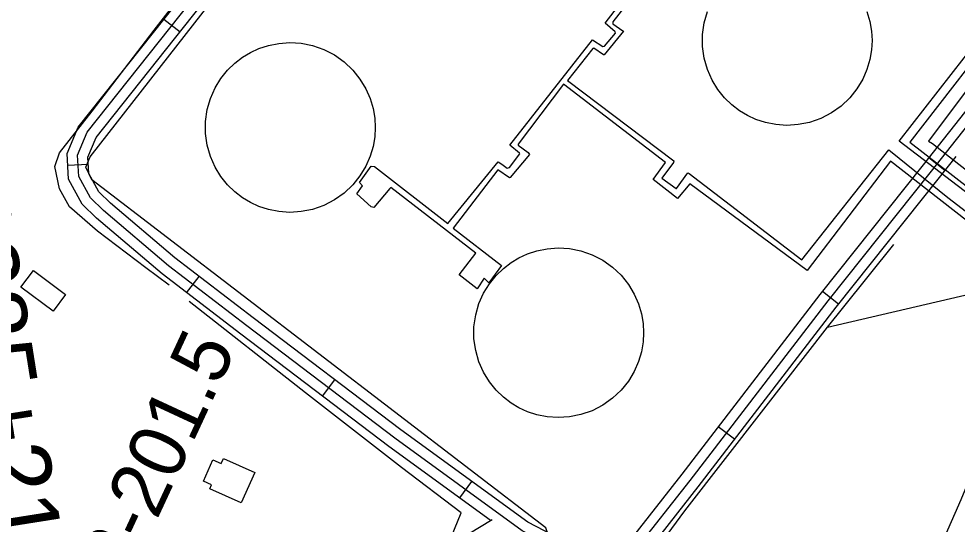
# Model space of a CAD drawing. Extents: x 3329332 to 3367211, y 631066 to 656469.
# Drawn here: x 3347258 to 3348632, y 645877 to 646618 of the extents above; entities that cross this region are included whole.
import ezdxf

# ---------------------------------------------------------------- set-up
doc = ezdxf.new("R2010")
doc.units = 0
for name, color, linetype in [('V-BLDG-OTLN', 7, 'Continuous'), ('V-DOMW-TANK', 7, 'Continuous'), ('V-RIVR-RANG-IDEN', 7, 'Continuous'), ('V-ROAD-CNTR', 7, 'Continuous'), ('V-SITE-OTLN', 7, 'Continuous'), ('V-SURV-IDEN', 7, 'Continuous'), ('V-TOPO-SHOR', 7, 'Continuous'), ('V-UTIL-LINE', 7, 'Continuous')]:
    doc.layers.add(name, color=color, linetype=linetype)

msp = doc.modelspace()

# ---------------------------------------------------------------- linework, layer by layer
at = {"layer": 'V-BLDG-OTLN'}
for points in [[(3347279.6, 646248.8), (3347326.4, 646213.6), (3347308.3, 646189.5), (3347261.4, 646224.7)], [(3347557.7, 645973.3), (3347603.6, 645952.9), (3347583.9, 645908.6), (3347537.9, 645929), (3347540.6, 645935.1), (3347528.6, 645940.4), (3347542.4, 645971.5), (3347554.5, 645966.1)]]:
    msp.add_lwpolyline(points, close=True, dxfattribs=at)
at = {"layer": 'V-DOMW-TANK'}
msp.add_lwpolyline([(3348500.2, 646628.3), (3348504.5, 646613.7), (3348506.9, 646599.6), (3348507.6, 646586), (3348506.9, 646572.4), (3348504.5, 646558.3), (3348500.2, 646543.7), (3348493.9, 646529.2), (3348485.5, 646515.1), (3348474.9, 646501.9), (3348462.3, 646490), (3348448, 646479.8), (3348432.4, 646471.8), (3348416, 646466), (3348399.2, 646462.7), (3348382.6, 646461.7), (3348366.6, 646462.8), (3348351.5, 646465.8), (3348337.6, 646470.4), (3348325, 646476.2), (3348313.5, 646483.1), (3348302.3, 646491.6), (3348291.6, 646502), (3348281.8, 646514.2), (3348273.3, 646528), (3348266.5, 646543.4), (3348261.7, 646559.9), (3348259.3, 646577.2), (3348259.3, 646594.8), (3348261.7, 646612.1), (3348266.5, 646628.6)], dxfattribs=at)
for points in [[(3347780, 646458.6), (3347779.3, 646445), (3347776.9, 646430.8), (3347772.6, 646416.3), (3347766.3, 646401.8), (3347757.8, 646387.7), (3347747.2, 646374.4), (3347734.6, 646362.5), (3347720.3, 646352.4), (3347704.8, 646344.3), (3347688.3, 646338.6), (3347671.6, 646335.3), (3347654.9, 646334.2), (3347638.9, 646335.4), (3347623.8, 646338.4), (3347609.9, 646342.9), (3347597.4, 646348.7), (3347585.9, 646355.7), (3347574.7, 646364.2), (3347564, 646374.6), (3347554.2, 646386.7), (3347545.7, 646400.6), (3347538.8, 646416), (3347534.1, 646432.5), (3347531.6, 646449.8), (3347531.6, 646467.4), (3347534.1, 646484.7), (3347538.8, 646501.2), (3347545.7, 646516.6), (3347554.2, 646530.4), (3347564, 646542.6), (3347574.7, 646552.9), (3347585.9, 646561.5), (3347597.4, 646568.4), (3347609.9, 646574.2), (3347623.8, 646578.8), (3347638.9, 646581.8), (3347654.9, 646582.9), (3347671.6, 646581.9), (3347688.3, 646578.6), (3347704.8, 646572.8), (3347720.3, 646564.8), (3347734.6, 646554.6), (3347747.2, 646542.7), (3347757.8, 646529.5), (3347766.3, 646515.4), (3347772.6, 646500.8), (3347776.9, 646486.3), (3347779.3, 646472.1)], [(3348173.1, 646157.7), (3348172.3, 646144.2), (3348170, 646130), (3348165.7, 646115.5), (3348159.4, 646101), (3348150.9, 646086.8), (3348140.3, 646073.6), (3348127.7, 646061.7), (3348113.4, 646051.6), (3348097.8, 646043.5), (3348081.4, 646037.8), (3348064.6, 646034.4), (3348048, 646033.4), (3348032, 646034.5), (3348016.9, 646037.5), (3348003, 646042.1), (3347990.5, 646047.9), (3347979, 646054.8), (3347967.8, 646063.4), (3347957.1, 646073.7), (3347947.3, 646085.9), (3347938.8, 646099.8), (3347931.9, 646115.1), (3347927.2, 646131.7), (3347924.7, 646149), (3347924.7, 646166.5), (3347927.2, 646183.8), (3347931.9, 646200.4), (3347938.8, 646215.7), (3347947.3, 646229.6), (3347957.1, 646241.7), (3347967.8, 646252.1), (3347979, 646260.7), (3347990.5, 646267.6), (3348003, 646273.4), (3348016.9, 646277.9), (3348032, 646280.9), (3348048, 646282.1), (3348064.6, 646281.1), (3348081.4, 646277.7), (3348097.8, 646272), (3348113.4, 646263.9), (3348127.7, 646253.8), (3348140.3, 646241.9), (3348150.9, 646228.6), (3348159.4, 646214.5), (3348165.7, 646200), (3348170, 646185.5), (3348172.3, 646171.3)]]:
    msp.add_lwpolyline(points, close=True, dxfattribs=at)
at = {"layer": 'V-ROAD-CNTR'}
for p, q in [((3347470.8, 646617.5), (3347494.3, 646598.9)), ((3347330.1, 646403.5), (3347360, 646405)), ((3348614.1, 646395.4), (3348590.5, 646414)), ((3347504, 646216.4), (3347522.2, 646240.2)), ((3348458.3, 646199.8), (3348434.9, 646218.4)), ((3347702.9, 646064.8), (3347721, 646088.7)), ((3348306.1, 646001.8), (3348282.3, 646020.1)), ((3347903.9, 645915.7), (3347921.5, 645939.9))]:
    msp.add_line(p, q, dxfattribs=at)
for points in [[(3348699.8, 648083.5), (3349088.4, 647776.5), (3349399.5, 647541.5), (3349419.1, 647509), (3349423.8, 647475), (3349412.3, 647441.3), (3349161.9, 647117.9), (3348937.1, 646838.3), (3348751.8, 646594.2), (3348594.4, 646394.7), (3348442.9, 646204.5), (3348240.8, 645941.3), (3348159.4, 645837.5), (3348124, 645794.7)], [(3348691.9, 648070.6), (3349079.3, 647764.6), (3349388.2, 647531.3), (3349404.7, 647503.9), (3349408.5, 647476.5), (3349398.9, 647448.5), (3349150.1, 647127.2), (3348925.3, 646847.5), (3348739.9, 646603.4), (3348582.6, 646404), (3348431.1, 646213.7), (3348228.9, 645950.5), (3348152.7, 645853.3)], [(3347948.4, 645883.3), (3347799.9, 645991.2), (3347583.1, 646155.7), (3347468, 646244), (3347372, 646325.6), (3347351.2, 646346.1), (3347331.1, 646382.7), (3347329.2, 646420.6), (3347345.1, 646459.1), (3347618.9, 646804.1), (3347951.1, 647231.7), (3348021, 647331.4), (3348308.8, 647701.3), (3348362.7, 647769.6), (3348463.5, 647894.9)], [(3348774.4, 645336.9), (3348736.7, 645375.5), (3348692.9, 645416.3), (3348640.3, 645440.7), (3348573.2, 645483.2), (3348460.3, 645542.1), (3348215.7, 645738.4), (3348118.5, 645798.1), (3348057.1, 645835.2), (3347995.4, 645867.7), (3347808.9, 646003.2), (3347592.2, 646167.7), (3347477.5, 646255.6), (3347382.2, 646336.7), (3347363.3, 646355.3), (3347345.9, 646386.9), (3347344.4, 646418), (3347358.2, 646451.5), (3347630.7, 646794.9), (3347963.2, 647222.8), (3348033.1, 647322.5), (3348320.6, 647692), (3348374.4, 647760.2), (3348475.2, 647885.5)], [(3348119.1, 645815.3), (3348064.5, 645848.3), (3348003.4, 645880.4), (3347817.8, 646015.3), (3347601.3, 646179.6), (3347486.9, 646267.3), (3347392.3, 646347.8), (3347375.4, 646364.4), (3347360.7, 646391.1), (3347359.5, 646415.3), (3347371.3, 646443.8), (3347642.5, 646785.6), (3347975.2, 647213.9), (3348045.2, 647313.6), (3348332.4, 647682.8), (3348386.1, 647750.9), (3348486.9, 647876.2)], [(3348630.5, 646416.2), (3348606.1, 646385.4), (3348454.8, 646195.3), (3348252.6, 645932.1), (3348177.1, 645835.8)], [(3348131.1, 645498.7), (3347974, 645620.5), (3347852.7, 645707), (3347841, 645737.3), (3347851.4, 645771.7), (3347916.7, 645863.1), (3347951.5, 645883.9)]]:
    msp.add_lwpolyline(points, dxfattribs=at)
at = {"layer": 'V-SITE-OTLN'}
for points in [[(3349704.8, 644526.5), (3349555.3, 644318.8), (3348877.5, 644783.3), (3348501.3, 645063.4), (3348672.5, 645295.1), (3348663.9, 645328.8), (3348637.1, 645365.8), (3348053.2, 645798.4), (3348030, 645871.8), (3347365.1, 646381.8), (3347356.3, 646400.3), (3347362.6, 646415.4), (3348646.5, 648060.7)], [(3348664.9, 648063.5), (3349371.7, 647510.1), (3349380.6, 647494.8), (3348590.2, 646438.5), (3348596.3, 646435.3), (3349236.9, 645931.8), (3349279, 645897.6), (3349765.2, 646596.4)]]:
    msp.add_lwpolyline(points, dxfattribs=at)
at = {"layer": 'V-TOPO-SHOR'}
for points in [[(3347478.6, 646227.3), (3347444, 646252.8), (3347373.4, 646306.8), (3347332.6, 646342.5), (3347317.7, 646368.9), (3347311.2, 646401.5), (3347317.9, 646421.2), (3347365.4, 646482.3), (3347456.6, 646601.3), (3347640.1, 646837.5), (3347729.9, 646953.3), (3347864.7, 647127.8), (3347951.8, 647236.1), (3348022.2, 647331.2), (3348264.4, 647644.9), (3348360.7, 647768.3), (3348525.3, 647979.3), (3348611.9, 648091.4)], [(3348153.6, 645787.7), (3348233.7, 645896.7), (3348348.9, 646045.9), (3348442.5, 646165.7), (3348466.1, 646195.8), (3348539.6, 646287.1)], [(3348442.5, 646165.7), (3348767, 646241.5), (3348780.9, 646272.5)], [(3348477.7, 645543.8), (3348502.6, 645602.7), (3348533.1, 645677.4), (3348571.1, 645763.2), (3348600.9, 645829), (3348638.2, 645913.5), (3348655.5, 645955.7), (3348678.1, 646015.2), (3348706.3, 646082.4), (3348737.1, 646158.1), (3348767, 646241.5)], [(3347694.7, 645403.6), (3347724.5, 645468.8), (3347779.5, 645600.5), (3347828.5, 645716.4), (3347876.7, 645822.1), (3347905.9, 645893.7), (3347818.4, 645960.1), (3347677.9, 646069.5), (3347507.9, 646203.5)]]:
    msp.add_lwpolyline(points, dxfattribs=at)
at = {"layer": 'V-UTIL-LINE'}
for points in [[(3347959.7, 646396.5), (3347894.3, 646311), (3347964.8, 646256.2), (3347946.7, 646230.8), (3347939.5, 646237.7), (3347929.5, 646222), (3347903, 646242.5), (3347927.3, 646274.5), (3347803.2, 646370.4), (3347801.3, 646369.2), (3347778.3, 646341.5), (3347774, 646342.2), (3347753, 646361.4), (3347761.7, 646372.9), (3347756.9, 646377.8), (3347774.4, 646401.9), (3347779.2, 646401.2), (3347886.5, 646317.8), (3347959.9, 646408.1), (3347965.3, 646405), (3347973.2, 646398.8), (3347976.8, 646399.9), (3347991.8, 646419.8), (3347991.2, 646421), (3347977.4, 646432.8), (3348098.1, 646587.1), (3348113.2, 646577.1), (3348115.7, 646577.6), (3348131.9, 646596.9), (3348131.3, 646598.7), (3348116.8, 646611.2), (3348187.8, 646704)], [(3348194.5, 646699), (3348127.8, 646613.4), (3348127.8, 646610.4), (3348142.9, 646600.4), (3348143.5, 646599.8), (3348115.5, 646564.8), (3348114.3, 646564.8), (3348100.4, 646574.8), (3348098.6, 646574.2), (3348061.8, 646527.3), (3348217.3, 646409.5), (3348216.7, 646407.1), (3348199.8, 646384.2), (3348220.9, 646369.2), (3348221.5, 646369.2), (3348237.8, 646392.1), (3348239.6, 646390.9), (3348404.7, 646264.4), (3348532.3, 646425.8), (3348534.7, 646424), (3348618.4, 646356.1), (3348646.1, 646335)], [(3348659.2, 646353.1), (3348547.1, 646438.4), (3348718.4, 646658.9)], [(3348709.9, 646626.7), (3348563, 646436.9), (3348843.1, 646219.6)], [(3348645.9, 646322.2), (3348534.5, 646409.3), (3348412.4, 646249), (3348240.6, 646376.2), (3348222.5, 646354.5), (3348187, 646382.5), (3348205.1, 646407.3), (3348055.6, 646521.9), (3347989.6, 646433.9), (3347989.6, 646432.7), (3348004, 646422.1), (3348005.8, 646419), (3347977.8, 646385.3), (3347976.6, 646384.7), (3347959.7, 646396.5)]]:
    msp.add_lwpolyline(points, dxfattribs=at)

# ---------------------------------------------------------------- texts
at = {"layer": 'V-RIVR-RANG-IDEN'}
msp.add_text('R-201.5', height=83, rotation=65.0981, dxfattribs=at).set_placement((3347410.9, 645776.1))
at = {"layer": 'V-SURV-IDEN'}
msp.add_text('1385+21.3', height=100, rotation=279.0303, dxfattribs=at).set_placement((3347141.7, 646359))

doc.saveas('drawing.dxf')
